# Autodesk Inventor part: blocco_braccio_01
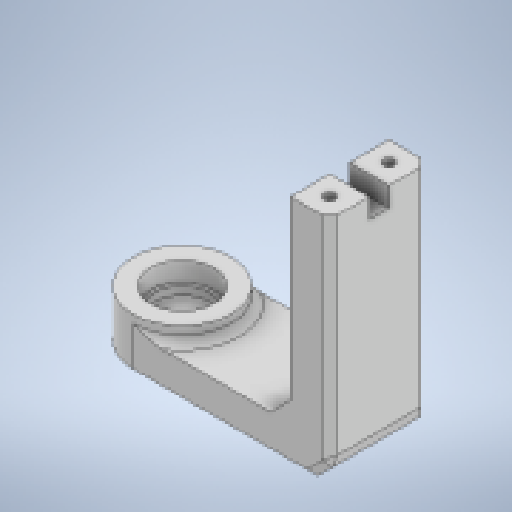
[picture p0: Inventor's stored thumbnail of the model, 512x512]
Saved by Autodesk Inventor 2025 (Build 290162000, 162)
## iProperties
Created: 2025-11
Part Number: blocco_braccio_01
Material: Generico
Document SubType Name: Modeling
Designer: Ryzen5700u
Density: 1 g/cm^3
Appearance: Default
Author: Ryzen5700u
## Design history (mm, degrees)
sketch "Schizzo1" dims "d0" = 25
  geometry: L1 (0, -12.5)-(-50, -12.5); L2 (-50, -12.5)-(-50, 12.5); L3 (-50, 12.5)-(0, 12.5); L4 (0, 12.5)-(0, -12.5); L5 (0, 0)-(-74.753, 0); 2 further points
  constraints: 10 end point, 2 horizontal, 2 parallel, 1 coincident, 1 perpendicular, 4 other
  dimensions: "d3" = 50 distance of L2.end L3.end; "d4" = 25 distance of L1.end L2.end
extrude "Estrusione1" new body sketch "Schizzo1" distance "d1" = 10; taper "d2" = 0 deg
node "Piano di lavoro1"
sketch "Schizzo2"
  geometry: L1 (50, 12.5)-(50, -12.5) reference; L2 (0, 12.5)-(50, 12.5) reference; L3 (50, -12.5)-(40, -12.5); L4 (40, -12.5)-(40, 12.5); L5 (40, 12.5)-(50, 12.5); L6 (50, 12.5)-(50, -12.5); L7 (40, -3)-(50, -3); L8 (50, -3)-(50, 3); L9 (50, 3)-(40, 3); L10 (40, 3)-(40, -3); L11 (0, 0)-(50, 0)
  constraints: 18 end point, 4 parallel, 3 perpendicular, 3 point on line, 2 horizontal, 1 midpoint, 1 other
  dimensions: "d5" = 10 distance of L4.end L5.end; "d6" = 6 distance of L8.end L7.end
extrude "Estrusione2" join sketch "Schizzo2" stored distance "d7" = 6; taper "d8" = 0 deg
node "Piano di lavoro2"
sketch "Schizzo4"
  geometry: C1 r 8 at (0, 0); 1 further point
  constraints: 1 centre point, 1 coincident
  dimensions: "d15" = 16 diameter of C1
extrude "Estrusione4" cut sketch "Schizzo4" distance "d16" = 3; taper "d17" = 0 deg
sketch "Schizzo5"
  geometry: C1 r 12.5 at (0, 0); C2 r 8 at (0, 0) reference; 1 further point
  constraints: 1 centre point, 1 coincident
  dimensions: "d30" = 25 diameter of C1
extrude "Estrusione5" join sketch "Schizzo5" distance "d18" = 4; taper "d19" = 0 deg
fillet "Raccordo2" dims "d20" = 2
sketch "Schizzo7"
  geometry: L1 (24.5, 15)-(-25.21, 15) reference; L2 (-25.21, 10)-(24.5, 10) reference; L3 (0, 25)-(0, 0) reference; L4 (10, 0)-(10, 25) reference; 5 further points
  node "Riferimento3"
  node "Riferimento4"
node "Piano di lavoro3"
extrude "Estrusione6" cut sketch "Schizzo7" stored distance "d21" = 4; taper "d22" = 0 deg
sketch "Schizzo8"
  geometry: L1 (0, 0)-(10, 0) reference; L2 (5, 0)-(5, 10); L3 (0, 10)-(10, 10) reference; L4 (10, 25)-(0, 25) reference; L5 (5, 25)-(5, 15); L6 (10, 15)-(0, 15) reference; 3 further points
  constraints: 6 midpoint, 4 end point
hole "Foro1" sketch "Schizzo8" at (5, 5), (5, 20) diameter "d23" = 2.7; stored, may be unused: countersink angle "d27" = 90 deg, drill point angle "d29" = 118 deg; dims "d24" = 6, "d25" = 5.5, "d26" = 2.9, "d28" = 12
sketch "Schizzo9"
  geometry: C1 r 7 at (0, 0); C2 r 8 at (0, 0) reference; 1 further point
  constraints: 1 centre point, 1 coincident
  dimensions: "d31" = 14 diameter of C1
extrude "Estrusione7" join sketch "Schizzo9" distance "d32" = 2; taper "d33" = 0 deg
chamfer "Smusso2" distance "d34" = 5; stored, may be unused: second distance "d35" = 2, angle "d36" = 45 deg
chamfer "Smusso3" distance "d37" = 2; stored, may be unused: second distance "d38" = 2, angle "d39" = 45 deg
node "Solido1"
